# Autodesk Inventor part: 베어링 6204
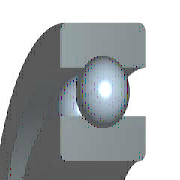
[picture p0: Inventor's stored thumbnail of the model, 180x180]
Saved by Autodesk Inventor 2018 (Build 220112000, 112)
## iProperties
Created: 2012-02
Part Number: 베어링 6204
Material: 강철, 연강
Description: 깊은 그루브 볼 베어링
Document SubType Name: Modeling
Standard: KS B 2023
Designer: mduedu
Standards Organization: KS
Language: ko-KR
Size Designation: 6204 - 20 x 47 x 14
Categories: <MemberInstance><Categories><Category DisplayName="샤프트 부품" InternalName="7f7aeb1f-a693-4053-b835-cee3144e0d98" Mnemonic="SHFT"><Category DisplayName="베어링" Inter
Density: 1 g/cm^3
Appearance: 노란색
IsCustomPart: 1
Author: mduedu
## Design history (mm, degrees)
sketch "스케치" dims "d0" = 7.02 (= -0.26 x WD + 0.26 x BD)
  geometry: L1 (3.49, 16.75)-(10.51, 16.75); L2 (7, 16.75)-(7, 13.24); L3 (7, 16.75)-(7, 20.26); L4 (4.392, 14.401)-(0, 14.401); L5 (0, 10)-(14, 10); L6 (4.392, 19.099)-(0, 19.099); L7 (0, 23.5)-(14, 23.5); L8 (14, 10)-(14, 14.401); L9 (9.608, 14.401)-(14, 14.401); L10 (9.608, 19.099)-(14, 19.099); L11 (14, 23.5)-(14, 19.099); L12 (-1.4, 0)-(8.4, 0) reference; L13 (0, -0.3)-(0, 5.3) reference
  constraints: 22 end point, 4 point on line, 2 collinear, 2 perpendicular, 2 symmetric about line, 1 midpoint, 1 parallel, 14 other
  dimensions: "d9" = 20 diameter of L5 L12 (= WD); "d11" = 47 diameter of L7 L12 (= BD); "d12" = 14 distance between parallel lines of L8 L13 (= KB); "d13" = 28.802 diameter of L9 L12 (= 0.326 x BD + 0.674 x WD)
revolve "본체" stored, may be unused: angle "d6" = 90 deg
revolve "볼" stored, may be unused: angle "d7" = 90 deg
pattern_circular "IDS_ARRAYBALL[SIMPL:T]" dims angle "d3" = 360 deg
body "Solid1"
fillet "모깎기1" dims "d1" = 1 (= KRS)
other parameters: "WD" = 20 [user parameter; used in 5 equation terms], "BD" = 47 [user parameter; used in 5 equation terms], "KB" = 14 [user parameter; used in 1 equation term], "KRS" = 1 [user parameter; used in 1 equation term], "d4" = 0, "d5" = 0, "d8" = 0, "d14" = 0, "d15" = 0, "BBA" = 0 [user parameter], "BC0" = 6550000 [user parameter], "BC" = 1.27e+07 [user parameter], "BR" = 23.5 (= 0.5 x BD) [user parameter]
